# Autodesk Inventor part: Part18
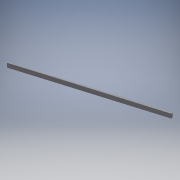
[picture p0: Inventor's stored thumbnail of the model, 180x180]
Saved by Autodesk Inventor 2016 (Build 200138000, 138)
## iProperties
Created: 2020-04
Part Number: Part18
Material: Generic
Document SubType Name: Modeling
Designer: merlin
Density: 1 g/cm^3
Appearance: Default
Author: merlin
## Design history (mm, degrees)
sketch "Sketch1"
  geometry: L1 (-147.637, -246.063)-(-301.625, -293.688); L2 (-301.625, -293.688)-(-302.366, -291.292); L3 (-302.366, -291.292)-(-148.008, -244.865); L4 (-148.008, -244.865)-(-147.637, -246.063); 1 further point
  constraints: 8 end point, 2 perpendicular
extrude "Extrusion1" new body sketch "Sketch1" distance "d0" = 5.08; taper "d1" = 0 deg
body "Solid1"
